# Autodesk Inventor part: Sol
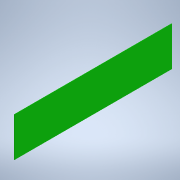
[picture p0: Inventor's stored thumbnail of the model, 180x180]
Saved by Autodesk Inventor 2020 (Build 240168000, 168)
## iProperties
Created: 2022-10
Part Number: Sol
Material: Générique
Document SubType Name: Modeling
Designer: bruno
Density: 1 g/cm^3
Appearance: Vert foncé
Author: bruno
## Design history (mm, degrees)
sketch "Esquisse1"
  geometry: L1 (0, 0)-(1000, 0); L2 (1000, 0)-(1000, -4000); L3 (1000, -4000)-(0, -4000); L4 (0, -4000)-(0, 0)
  constraints: 8 end point, 2 parallel, 1 horizontal, 1 perpendicular
  dimensions: "d0" = 1000 distance of L2.end L3.end; "d1" = 4000 distance of L1.end L2.end
extrude "Extrusion1" new body sketch "Esquisse1" distance "d2" = 10; taper "d3" = 0 deg
sketch "Esquisse2"
  geometry: L1 (-3773.641, 444.733)-(-3773.641, 488.483) reference; L2 (-3769.641, 491.608)-(-3773.641, 491.608) reference; C1 r 1.595 at (-3769.641, 491.608); 1 further point
  constraints: 1 centre point, 1 coincident
extrude "Extrusion2" join sketch "Esquisse2" distance "d4" = 150; taper "d5" = 0 deg
node "Solide1"
node "Référence1"
node "Référence2"
